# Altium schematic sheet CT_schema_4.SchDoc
size 401 x 230 mm
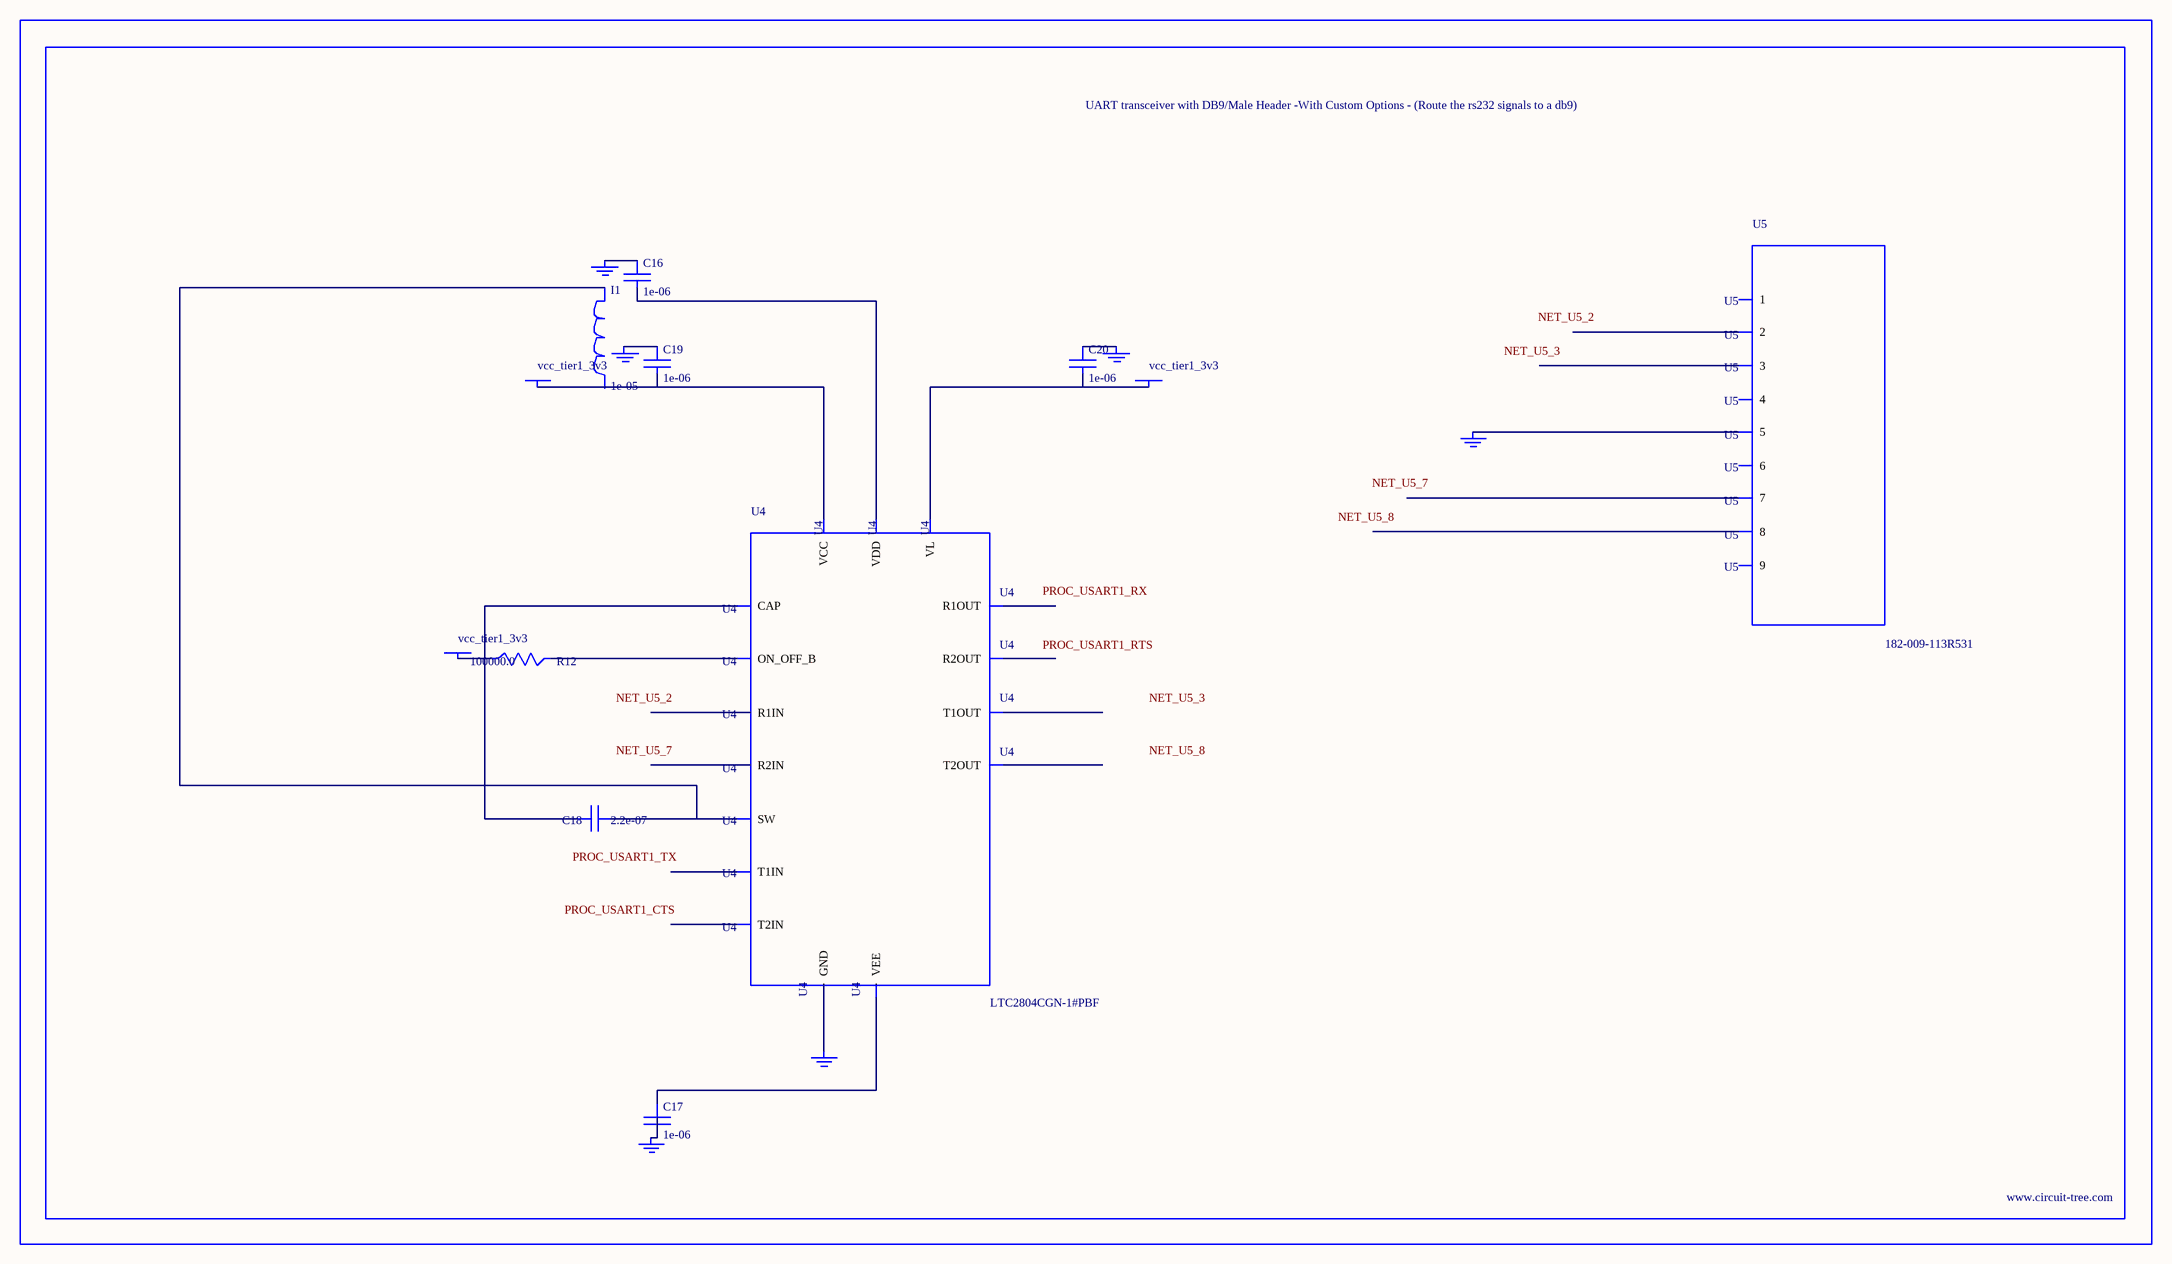
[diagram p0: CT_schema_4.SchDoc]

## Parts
BORDER3  (no value)
C16  1e-06  [C0603]
C17  1e-06  [C0603]
C18  2.2e-07  [C0603]
C19  1e-06  [C0603]
C20  1e-06  [C0603]
GND_INSTANCE_3_0  (no value)
GND_INSTANCE_3_1  (no value)
GND_INSTANCE_3_2  (no value)
GND_INSTANCE_3_3  (no value)
GND_INSTANCE_3_4  (no value)
GND_INSTANCE_3_5  (no value)
I1  1e-05  [L1210]
POWER_INSTANCE_3_0  vcc_tier1_3v3
POWER_INSTANCE_3_1  vcc_tier1_3v3
POWER_INSTANCE_3_2  vcc_tier1_3v3
R12  100000.0  [R0603]
U4  LTC2804CGN-1#PBF  [SSOP-16]
U5  182-009-113R531  [182-009-MALE]

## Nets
NetC16_1: C16.1 GND_INSTANCE_3_1.0(GND)
NetC16_2: C16.2 U4.6(VDD)
NetC17_1: C17.1 U4.9(VEE)
NetC17_2: C17.2 GND_INSTANCE_3_2.0(GND)
NetC18_1: C18.1 I1.1 U4.7(SW)
NetC18_2: C18.2 U4.10(CAP)
NetC19_1: C19.1 GND_INSTANCE_3_0.0(GND)
NetC19_2: C19.2 POWER_INSTANCE_3_0.0(PWR) U4.5(VCC)
NetC20_1: C20.1 GND_INSTANCE_3_3.0(GND)
NetC20_2: C20.2 POWER_INSTANCE_3_2.0(PWR) U4.12(VL)
NetGND_INSTANCE_3_4_0: GND_INSTANCE_3_4.0(GND) U4.8(GND)
NetGND_INSTANCE_3_5_0: GND_INSTANCE_3_5.0(GND) U5.5
NetPOWER_INSTANCE_3_1_0: POWER_INSTANCE_3_1.0(PWR) R12.1
NetR12_2: R12.2 U4.11(ON_OFF_B)

Not connected (* = marked no-connect by the designer): I1 2; U4 1(R1IN) 2(R2IN) 3(T1OUT) 4(T2OUT) 13(T2IN) 14(T1IN) 15(R2OUT) 16(R1OUT); U5 1 2 3 4 6 7 8 9

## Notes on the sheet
- Labels drawn without touching a wire or pin: NET_U5_2, NET_U5_3, NET_U5_7, NET_U5_8, PROC_USART1_CTS, PROC_USART1_RTS, PROC_USART1_RX, PROC_USART1_TX

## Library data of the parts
BORDER3 = BORDER_PAGE3
C16 C17 C19 C20 = C0603C105K3RACTU
C18 = C0603C224K3RAC
GND_INSTANCE_3_0-GND_INSTANCE_3_5 = GND
I1 = CBC3225T100MR
POWER_INSTANCE_3_0-POWER_INSTANCE_3_2 = PWR
R12 = RC0603JR-07100KL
